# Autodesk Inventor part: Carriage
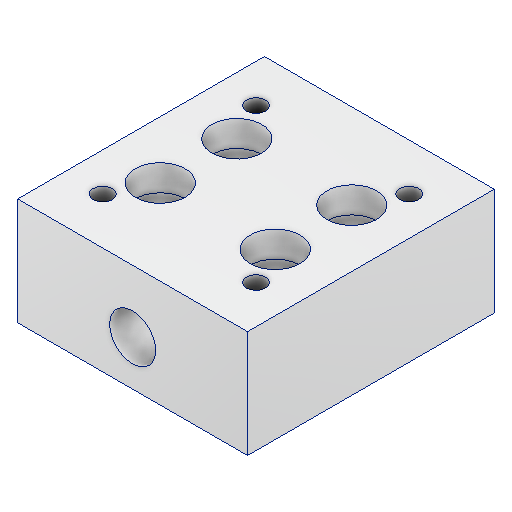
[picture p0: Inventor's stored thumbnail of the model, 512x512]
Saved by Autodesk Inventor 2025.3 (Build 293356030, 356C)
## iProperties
Created: 2021-07
Part Number: Carriage
Material: Alluminio 6061
Document SubType Name: Modeling
Designer: R5800u
Density: 2.7 g/cm^3
Appearance: Alluminio - Piatto
Sending System: SolidWorks 2021
Last Author: Albert
Last Saved: 2021-07-29
Author: R5800u
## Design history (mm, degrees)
hole "Hole2"
node "Плоскость4"
sketch "Schizzo1"
  geometry: C1 r 2.75 at (15, 5.85) reference; 2 further points
  constraints: 1 coincident
hole "Foro1" sketch "Schizzo1" at (15, 5.85) diameter "d0" = 6; stored, may be unused: countersink angle "d4" = 82 deg, drill point angle "d6" = 118 deg; dims "d1" = 6, "d2" = 3.023, "d3" = 2, "d5" = 8.8
node "Piano di lavoro2"
sketch "Schizzo2"
  geometry: L1 (26.573, 8.201)-(18.765, 8.201); L2 (18.765, 8.201)-(18.765, 23.937); L3 (18.765, 23.937)-(26.573, 23.937); L4 (26.573, 23.937)-(26.573, 8.201); L5 (11.275, 8.201)-(3.866, 8.201); L6 (3.866, 8.201)-(3.866, 23.937); L7 (3.866, 23.937)-(11.275, 23.937); L8 (11.275, 23.937)-(11.275, 8.201); 1 further point
  constraints: 16 end point, 4 parallel, 2 horizontal, 2 perpendicular, 2 point on line
extrude "Estrusione1" join sketch "Schizzo2" stored distance "d7" = 10; taper "d8" = 0 deg
sketch "Schizzo3"
  geometry: L1 (5, 0)-(0, 0) reference; L2 (0, -10)-(5, -10) reference; C1 r 5 at (2.5, -5); A1 r 5 centre (2.5, -5) between (2.5, 0) and (2.5, -10) reference; A2 r 5 centre (5, -5) between (5, -10) and (5, 0) reference; 5 further points
  constraints: 1 centre point, 1 coincident, 1 tangent
extrude "Estrusione2" cut sketch "Schizzo3" stored distance "d9" = 10; taper "d10" = 0 deg
sketch "Schizzo4"
  geometry: C1 r 1.25 at (22.5, 11.1) reference; C2 r 1.25 at (22.5, 21.1) reference; C3 r 1.25 at (7.5, 21.1) reference; C4 r 1.25 at (7.5, 11.1) reference; C5 r 1.25 at (25, 6.1) reference; C6 r 1.25 at (5, 26.1) reference; C7 r 1.25 at (25, 26.1) reference; 4 further points
  constraints: 3 coincident
hole "Foro2" sketch "Schizzo4" at (7.5, 11.1), (22.5, 11.1), (22.5, 21.1), (7.5, 21.1) diameter "d11" = 3.2; stored, may be unused: countersink angle "d15" = 90 deg, drill point angle "d17" = 118 deg; dims "d12" = 6, "d13" = 6.5, "d14" = 3.4, "d16" = 8.8
sketch "Schizzo5"
  geometry: C1 r 1.25 at (25, 26.1) reference; C2 r 1.25 at (5, 26.1) reference; C3 r 1.25 at (25, 6.1) reference; C4 r 1.25 at (5, 6.1) reference; 5 further points
  constraints: 4 coincident
hole "Foro3" sketch "Schizzo5" at (25, 26.1), (5, 26.1), (25, 6.1), (5, 6.1) diameter "d18" = 2.459; stored, may be unused: countersink angle "d22" = 82 deg, drill point angle "d24" = 118 deg; dims "d19" = 6, "d20" = 3.023, "d21" = 2, "d23" = 8.8
node "Solido1"
node "Riferimento1"
node "Riferimento2"
node "Riferimento3"
node "Riferimento4"
